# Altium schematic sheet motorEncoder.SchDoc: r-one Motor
size A; Date: 08/09/2011; DrawnBy: MRSL; Engineer: MRSL; Organization: Rice University; Revision: V11; SheetNumber: roneV11-motorEncoder; SheetTotal: 6
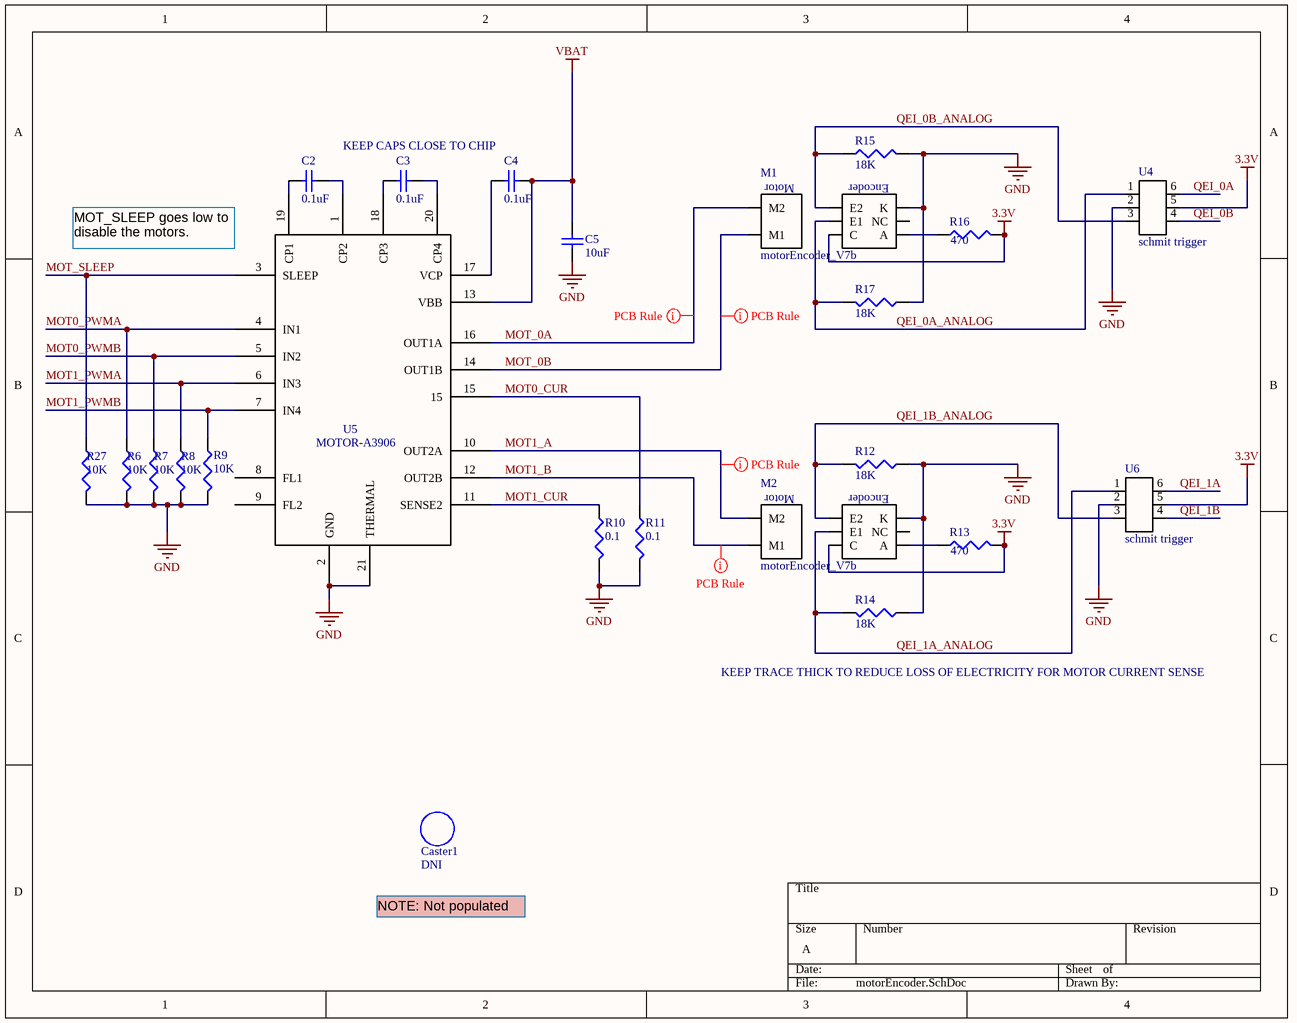
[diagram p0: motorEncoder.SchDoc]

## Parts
C2  value 0.1uF  [CAPC1005L]  (hidden comment: Cap Semi)
C3  value 0.1uF  [CAPC1005L]  (hidden comment: Cap Semi)
C4  value 0.1uF  [CAPC1005L]  (hidden comment: Cap Semi)
C5  value 10uF  [CAPC1608L]  (hidden comment: Cap Semi)
Caster1  non connect  [3/4"CASTER2]  (value not drawn)
M1  motorEncoder_V7b  [motorEncoder_V7b]
M2  motorEncoder_V7b  [motorEncoder_V7b]
R6  value 10K  [RESC1608L]  (hidden comment: Res3)
R7  value 10K  [RESC1608L]  (hidden comment: Res3)
R8  value 10K  [RESC1608L]  (hidden comment: Res3)
R9  value 10K  [RESC1608L]  (hidden comment: Res3)
R10  value 0.1  [RESC1608L]  (hidden comment: Res3)
R11  value 0.1  [RESC1608L]  (hidden comment: Res3)
R12  value 18K  [RESC1608L]
R13  value 470  [RESC1608L]
R14  value 18K  [RESC1608L]
R15  value 18K  [RESC1608L]
R16  value 470  [RESC1608L]
R17  value 18K  [RESC1608L]
R27  value 10K  [CAPC1608L]  (hidden comment: Res3)
U4  schmit trigger  [DCK(R-PDSO-C6)]
U5  MOTOR-A3906  [QFN-20]
U6  schmit trigger  [DCK(R-PDSO-C6)]

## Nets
3.3V: M1.C M2.C R13.2 R16.2 U4.5 U6.5
GND: C5.1 M1.K M2.K R6.2 R7.2 R8.2 R9.2 R10.2 R11.2 R12.1 R14.1 R15.2 R17.1 R27.2 U4.2 U5.2(GND) U5.21(THERMAL) U6.2
VBAT: C4.1 C5.2 U5.13(VBB)
MOT0_CUR: R11.1 U5.15
MOT0_PWMA: R6.1 U5.4(IN1)
MOT0_PWMB: R7.1 U5.5(IN2)
MOT1_A: M2.M2 U5.10(OUT2A)
MOT1_B: M2.M1 U5.12(OUT2B)
MOT1_CUR: R10.1 U5.11(SENSE2)
MOT1_PWMA: R8.1 U5.6(IN3)
MOT1_PWMB: R9.1 U5.7(IN4)
MOT_0A: M1.M2 U5.16(OUT1A)
MOT_0B: M1.M1 U5.14(OUT1B)
MOT_SLEEP: R27.1 U5.3(SLEEP)
QEI_0A: U4.6
QEI_0A_ANALOG: M1.E1 R17.2 U4.1
QEI_0B: U4.4
QEI_0B_ANALOG: M1.E2 R15.1 U4.3
QEI_1A: U6.6
QEI_1A_ANALOG: M2.E1 R14.2 U6.1
QEI_1B: U6.4
QEI_1B_ANALOG: M2.E2 R12.2 U6.3
NetC2_1: C2.1 U5.19(CP1)
NetC2_2: C2.2 U5.1(CP2)
NetC3_1: C3.1 U5.18(CP3)
NetC3_2: C3.2 U5.20(CP4)
NetC4_2: C4.2 U5.17(VCP)
NetM1_A: M1.A R16.1
NetM2_A: M2.A R13.1

Not connected (* = marked no-connect by the designer): M1 NC; M2 NC; U5 8(FL1) 9(FL2)

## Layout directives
rule Width Constraint [Pref Width = 20mil    Min Width = 10mil    Max Width = 25mil]: MOT1_A, MOT1_B, MOT_0A, MOT_0B

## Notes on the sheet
- KEEP CAPS CLOSE TO CHIP
- (near U5) MOT_SLEEP goes low to disable the motors.
- KEEP TRACE THICK TO REDUCE LOSS OF ELECTRICITY FOR MOTOR CURRENT SENSE
- NOTE: Not populated

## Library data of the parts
C2-C4 = Cap Semi: Capacitor (Semiconductor SIM Model); Part Number: GRM155R71C104KA88D; Manufacturer: Murata
C5 = Cap Semi: Capacitor (Semiconductor SIM Model); Part Number: GRM188R60J106ME47J; Manufacturer: Murata
Caster1 = Caster 3/4in: This is just a space saver to get the caster onto the pcb; Part Number: 955; Manufacturer: Pololu
M1 M2 = motorEncoder_V7b: Part Number: EE-SX1131; Manufacturer: Omron
R6-R9 R27 = Res3: Resistor; Part Number: 71-CRCW0603-10K-E3; Manufacturer: Vishay Dale
R10 R11 = Res3: Resistor; Part Number: ERJ-3RSJR10V; Manufacturer: Panasonic
R12 R14 R15 R17 = Res3: Resistor; Part Number: ERJ-3GEYJ183V; Manufacturer: Panasonic
R13 R16 = Res3: Resistor; Part Number: ERJ-3GEYJ471V; Manufacturer: Panasonic
U4 U6 = schmit trigger: Part Number: SN74LVC2G17QDCKRQ1; Manufacturer: TI
U5 = MOTOR-A3906: Part Number: A3906SESTR-T; Manufacturer: Allegro Micro Systems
